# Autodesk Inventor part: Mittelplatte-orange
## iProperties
Created: 2004-10
Part Number: Mittelplatte-orange
Document SubType Name: Modeling
Designer: sahrens
Manufacturer: Standard
Standards Organization: Custom
Author: sahrens
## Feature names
1. Extrusion1
2. Extrusion2
3. Rundung2 [Fillet]
